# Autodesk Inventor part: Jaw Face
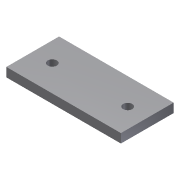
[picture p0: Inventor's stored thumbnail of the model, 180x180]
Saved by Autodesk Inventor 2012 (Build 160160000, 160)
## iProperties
Shininess: 77.0
Length Units: 11269
Angle Units: 11279
Time Units: 11290
Mass Units: 11283
Length Display Precision: 3
Angle Display Precision: 2
Compacted: True
Created: 2002-02
Part Number: Jaw Face
Document SubType Name: Modeling
Designer: ***
Density: 1 g/cm^3
Material: Default
Mass: 15.6207 g
Surface Area: 67.651 cm^2
Volume: 15.6207 cm^3
Density: 0.0
Volumn: 0.0
Area: 0.0
PropertySet Name: Model Information
Control State: 0
Master: False
Checked Out: False
Author: ***
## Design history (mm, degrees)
sketch "Sketch1"
  geometry: L1 (-79.661, -8.43)-(-3.661, -8.43); L2 (-3.661, -8.43)-(-3.661, -43.43); L3 (-3.661, -43.43)-(-79.661, -43.43); L4 (-79.661, -43.43)-(-79.661, -8.43); C1 r 3 at (-66.661, -25.93); C2 r 3 at (-16.661, -25.93)
  constraints: 8 end point, 2 centre point, 2 parallel, 1 equal radius, 1 horizontal, 1 perpendicular
  dimensions: "d0" = 76 distance of L2.end L3.end; "d1" = 6 diameter of C1; "d2" = 50 distance of C2.centre C1.centre; "d3" = 35 distance of L1.end L2.end; "d4" = 17.5 distance from line of L3 C2.centre; "d5" = 13 distance from line of L2 C2.centre; "d6" = 13 distance from line of L4 C1.centre
extrude "Extrusion1" new body sketch "Sketch1" stored distance "d7" = 6; taper "d8" = 0 deg
body "Solid1"
